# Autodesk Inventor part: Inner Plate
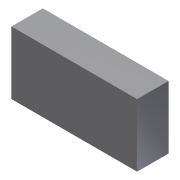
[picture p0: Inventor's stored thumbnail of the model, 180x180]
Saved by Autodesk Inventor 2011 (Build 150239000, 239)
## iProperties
Created: 2010-04
Part Number: Inner Plate
Document SubType Name: Modeling
Designer: CADSoft
Density: 1 g/cm^3
Author: CADSoft
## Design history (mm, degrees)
sketch "Sketch1"
  geometry: L1 (-20.23, -7.511)-(19.77, -7.511); L2 (19.77, -7.511)-(19.77, 12.489); L3 (19.77, 12.489)-(-20.23, 12.489); L4 (-20.23, 12.489)-(-20.23, -7.511); 1 further point
  constraints: 8 end point, 2 parallel, 1 horizontal, 1 perpendicular
workplane "Work Plane1"
extrude "Extrusion1" new body sketch "Sketch1" stored distance "d0" = 25.4; taper "d1" = 0 deg
body "Solid1"
